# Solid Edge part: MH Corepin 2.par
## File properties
Author: davee
Template: MH Die Plate.par
Last saved by: davee
Revision: 10
Application: Solid Edge
Accuracy: 0.99
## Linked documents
MH Die Plate.par
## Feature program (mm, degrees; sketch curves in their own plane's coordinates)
part copy "CopiedPart_1"
sketch for "ExtrudedCutout_1" plane through (0, 0, 0) normal (0, -1, 0) x-axis (1, 0, 0)
extrude "ExtrudedCutout_1" cut finite 89 along -normal
sketch for "ExtrudedProtrusion_1" plane through (-19, 100, -11.37) normal (0, 1, 0) x-axis (-1, 0, 0)
  circle centre (0, 1.22) radius 5
extrude "ExtrudedProtrusion_1" add finite 40 along +normal
sketch for "ExtrudedProtrusion_2" plane through (-19, 140, -11.37) normal (0, 1, 0) x-axis (-1, 0, 0)
  circle centre (0, 1.22) radius 8
extrude "ExtrudedProtrusion_2" add finite 5 along -normal
sketch for "unnamed Cutout 1" plane through (-19, 140, -11.37) normal (0, 1, 0) x-axis (-1, 0, 0)
  line (-7.8768, 6.22) -> (13.5216, 6.22)
extrude "unnamed Cutout 1" cut through along -normal
delete faces "unnamed DeleteFaces 1"
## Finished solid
Body 1: solid body, 15 faces, 25 edges, 13 vertices.
  Faces by surface: plane 9, cylinder 5, cone 1
  Edges by curve: line 13, circle 12
Bounding box of the edges (mm): 16.000 x 73.195 x 13.000, from (-27, 66.805, -18.15) to (-11, 140, -5.15).
Cylindrical faces by radius (mm): R1.1165 x1, R1.6747 x1, R2.233 x1, R5 x1, R8 x1
Conical faces (half-angle, radius in mm at the cone's reference point): 59 deg R2.233 x1
Planar faces by outward normal: +y 1, +z 2, -y 5, -z 1
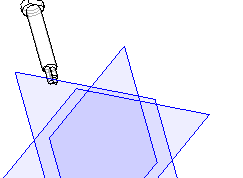
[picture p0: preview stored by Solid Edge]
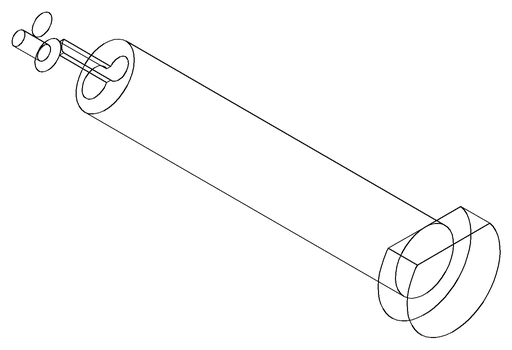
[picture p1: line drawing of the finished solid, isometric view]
